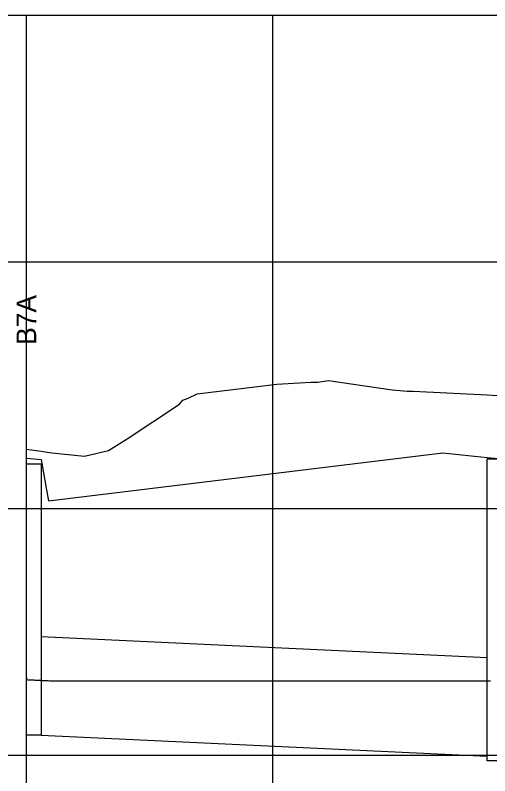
# Model space of a CAD drawing. Extents: x 2254979 to 2278074, y 13790855 to 13792793.
# Drawn here: x 2277948.3 to 2277996.4, y 13792714.2 to 13792791.3 of the extents above; entities that cross this region are included whole.
import ezdxf

# ---------------------------------------------------------------- set-up
doc = ezdxf.new("R2010")
doc.units = 0
for name, color, linetype in [('blank4', 7, 'Continuous'), ('BORD_grid_bottom_major_5int', 7, 'Continuous'), ('D_DRN_PROF_HGL', 7, 'Continuous'), ('D_PROF_1', 7, 'Continuous'), ('D_PROF_NOTES_1', 7, 'Continuous'), ('Drain_PipeInside', 7, 'Continuous'), ('E_Terrain', 7, 'Continuous'), ('Inlet', 7, 'Continuous'), ('z - Construction', 7, 'Continuous')]:
    doc.layers.add(name, color=color, linetype=linetype)

msp = doc.modelspace()

# ---------------------------------------------------------------- linework, layer by layer
at = {"layer": 'blank4'}
msp.add_lwpolyline([(2277949.404, 13792691.266), (2277949.404, 13792766.266), (2278029.904, 13792766.266), (2278029.904, 13792691.266)], close=True, dxfattribs=at)
at = {"layer": 'BORD_grid_bottom_major_5int'}
for p, q in [((2277749.404, 13792791.266), (2278074.404, 13792791.266)), ((2277949.404, 13792491.266), (2277949.404, 13792791.266)), ((2277974.404, 13792491.266), (2277974.404, 13792791.266)), ((2277749.404, 13792766.266), (2278074.404, 13792766.266)), ((2277749.404, 13792741.266), (2278074.404, 13792741.266)), ((2277749.404, 13792716.266), (2278074.404, 13792716.266))]:
    msp.add_line(p, q, dxfattribs=at)
at = {"layer": 'D_DRN_PROF_HGL'}
msp.add_lwpolyline([(2277949.404, 13792724.148), (2277949.404, 13792723.932), (2277949.432, 13792723.935), (2277949.536, 13792723.93), (2277949.641, 13792723.925), (2277949.745, 13792723.92), (2277949.85, 13792723.915), (2277949.954, 13792723.911), (2277950.059, 13792723.906), (2277950.163, 13792723.901), (2277950.268, 13792723.896), (2277950.372, 13792723.891), (2277950.477, 13792723.886), (2277950.581, 13792723.882), (2277950.686, 13792723.877), (2277950.79, 13792723.872), (2277950.895, 13792723.867), (2277950.999, 13792723.862), (2277951.104, 13792723.858), (2277951.208, 13792723.853), (2277951.313, 13792723.848), (2277951.417, 13792723.843), (2277951.522, 13792723.838), (2277951.627, 13792723.833), (2277951.731, 13792723.829), (2277951.836, 13792723.824), (2277951.94, 13792723.819), (2277952.045, 13792723.814), (2277952.15, 13792723.809), (2277952.254, 13792723.805), (2277952.359, 13792723.8), (2277952.463, 13792723.798), (2277952.568, 13792723.798), (2277952.673, 13792723.798), (2277952.777, 13792723.798), (2277952.882, 13792723.798), (2277952.987, 13792723.798), (2277953.091, 13792723.798), (2277953.196, 13792723.798), (2277953.301, 13792723.798), (2277953.406, 13792723.798), (2277953.51, 13792723.798), (2277953.615, 13792723.799), (2277953.72, 13792723.799), (2277953.824, 13792723.799), (2277953.929, 13792723.799), (2277954.034, 13792723.799), (2277954.139, 13792723.799), (2277954.243, 13792723.799), (2277954.348, 13792723.799), (2277954.453, 13792723.799), (2277954.558, 13792723.799), (2277954.663, 13792723.799), (2277954.767, 13792723.799), (2277954.872, 13792723.8), (2277954.977, 13792723.8), (2277955.082, 13792723.8), (2277955.187, 13792723.8), (2277955.291, 13792723.8), (2277955.396, 13792723.8), (2277955.501, 13792723.8), (2277955.606, 13792723.8), (2277955.711, 13792723.8), (2277955.816, 13792723.8), (2277955.921, 13792723.8), (2277956.025, 13792723.8), (2277956.13, 13792723.8), (2277956.235, 13792723.801), (2277956.34, 13792723.801), (2277956.445, 13792723.801), (2277956.55, 13792723.801), (2277956.655, 13792723.801), (2277956.76, 13792723.801), (2277956.865, 13792723.801), (2277956.97, 13792723.801), (2277957.075, 13792723.801), (2277957.179, 13792723.801), (2277957.284, 13792723.801), (2277957.389, 13792723.801), (2277957.494, 13792723.801), (2277957.599, 13792723.801), (2277957.704, 13792723.802), (2277957.809, 13792723.802), (2277957.914, 13792723.802), (2277958.019, 13792723.802), (2277958.124, 13792723.802), (2277958.229, 13792723.802), (2277958.334, 13792723.802), (2277958.439, 13792723.802), (2277958.544, 13792723.802), (2277958.649, 13792723.802), (2277958.754, 13792723.802), (2277958.859, 13792723.802), (2277958.964, 13792723.802), (2277959.069, 13792723.802), (2277959.174, 13792723.802), (2277959.279, 13792723.803), (2277959.385, 13792723.803), (2277959.49, 13792723.803), (2277959.595, 13792723.803), (2277959.7, 13792723.803), (2277959.805, 13792723.803), (2277959.91, 13792723.803), (2277960.015, 13792723.803), (2277960.12, 13792723.803), (2277960.225, 13792723.803), (2277960.33, 13792723.803), (2277960.435, 13792723.803), (2277960.541, 13792723.803), (2277960.646, 13792723.803), (2277960.751, 13792723.803), (2277960.856, 13792723.804), (2277960.961, 13792723.804), (2277961.066, 13792723.804), (2277961.171, 13792723.804), (2277961.277, 13792723.804), (2277961.382, 13792723.804), (2277961.487, 13792723.804), (2277961.592, 13792723.804), (2277961.697, 13792723.804), (2277961.802, 13792723.804), (2277961.908, 13792723.804), (2277962.013, 13792723.804), (2277962.118, 13792723.804), (2277962.223, 13792723.804), (2277962.328, 13792723.804), (2277962.434, 13792723.804), (2277962.539, 13792723.804), (2277962.644, 13792723.805), (2277962.749, 13792723.805), (2277962.854, 13792723.805), (2277962.96, 13792723.805), (2277963.065, 13792723.805), (2277963.17, 13792723.805), (2277963.275, 13792723.805), (2277963.381, 13792723.805), (2277963.486, 13792723.805), (2277963.591, 13792723.805), (2277963.696, 13792723.805), (2277963.802, 13792723.805), (2277963.907, 13792723.805), (2277964.012, 13792723.805), (2277964.118, 13792723.805), (2277964.223, 13792723.805), (2277964.328, 13792723.805), (2277964.433, 13792723.806), (2277964.539, 13792723.806), (2277964.644, 13792723.806), (2277964.749, 13792723.806), (2277964.855, 13792723.806), (2277964.96, 13792723.806), (2277965.065, 13792723.806), (2277965.171, 13792723.806), (2277965.276, 13792723.806), (2277965.381, 13792723.806), (2277965.487, 13792723.806), (2277965.592, 13792723.806), (2277965.697, 13792723.806), (2277965.803, 13792723.806), (2277965.908, 13792723.806), (2277966.013, 13792723.806), (2277966.119, 13792723.806), (2277966.224, 13792723.806), (2277966.33, 13792723.806), (2277966.435, 13792723.807), (2277966.54, 13792723.807), (2277966.646, 13792723.807), (2277966.751, 13792723.807), (2277966.857, 13792723.807), (2277966.962, 13792723.807), (2277967.067, 13792723.807), (2277967.173, 13792723.807), (2277967.278, 13792723.807), (2277967.384, 13792723.807), (2277967.489, 13792723.807), (2277967.594, 13792723.807), (2277967.7, 13792723.807), (2277967.805, 13792723.807), (2277967.911, 13792723.807), (2277968.016, 13792723.807), (2277968.122, 13792723.807), (2277968.227, 13792723.807), (2277968.333, 13792723.807), (2277968.438, 13792723.807), (2277968.543, 13792723.807), (2277968.649, 13792723.808), (2277968.754, 13792723.808), (2277968.86, 13792723.808), (2277968.965, 13792723.808), (2277969.071, 13792723.808), (2277969.176, 13792723.808), (2277969.282, 13792723.808), (2277969.387, 13792723.808), (2277969.493, 13792723.808), (2277969.598, 13792723.808), (2277969.704, 13792723.808), (2277969.809, 13792723.808), (2277969.915, 13792723.808), (2277970.02, 13792723.808), (2277970.126, 13792723.808), (2277970.231, 13792723.808), (2277970.337, 13792723.808), (2277970.442, 13792723.808), (2277970.548, 13792723.808), (2277970.653, 13792723.808), (2277970.759, 13792723.808), (2277970.865, 13792723.808), (2277970.97, 13792723.809), (2277971.076, 13792723.809), (2277971.181, 13792723.809), (2277971.287, 13792723.809), (2277971.392, 13792723.809), (2277971.498, 13792723.809), (2277971.603, 13792723.809), (2277971.709, 13792723.809), (2277971.815, 13792723.809), (2277971.92, 13792723.809), (2277972.026, 13792723.809), (2277972.131, 13792723.809), (2277972.237, 13792723.809), (2277972.343, 13792723.809), (2277972.448, 13792723.809), (2277972.554, 13792723.809), (2277972.659, 13792723.809), (2277972.765, 13792723.809), (2277972.871, 13792723.809), (2277972.976, 13792723.809), (2277973.082, 13792723.809), (2277973.187, 13792723.809), (2277973.293, 13792723.809), (2277973.399, 13792723.809), (2277973.504, 13792723.81), (2277973.61, 13792723.81), (2277973.715, 13792723.81), (2277973.821, 13792723.81), (2277973.927, 13792723.81), (2277974.032, 13792723.81), (2277974.138, 13792723.81), (2277974.244, 13792723.81), (2277974.349, 13792723.81), (2277974.455, 13792723.81), (2277974.561, 13792723.81), (2277974.666, 13792723.81), (2277974.772, 13792723.81), (2277974.878, 13792723.81), (2277974.983, 13792723.81), (2277975.089, 13792723.81), (2277975.195, 13792723.81), (2277975.3, 13792723.81), (2277975.406, 13792723.81), (2277975.512, 13792723.81), (2277975.617, 13792723.81), (2277975.723, 13792723.81), (2277975.829, 13792723.81), (2277975.935, 13792723.81), (2277976.04, 13792723.81), (2277976.146, 13792723.81), (2277976.252, 13792723.811), (2277976.357, 13792723.811), (2277976.463, 13792723.811), (2277976.569, 13792723.811), (2277976.675, 13792723.811), (2277976.78, 13792723.811), (2277976.886, 13792723.811), (2277976.992, 13792723.811), (2277977.097, 13792723.811), (2277977.203, 13792723.811), (2277977.309, 13792723.811), (2277977.415, 13792723.811), (2277977.52, 13792723.811), (2277977.626, 13792723.811), (2277977.732, 13792723.811), (2277977.838, 13792723.811), (2277977.943, 13792723.811), (2277978.049, 13792723.811), (2277978.155, 13792723.811), (2277978.261, 13792723.811), (2277978.366, 13792723.811), (2277978.472, 13792723.811), (2277978.578, 13792723.811), (2277978.684, 13792723.811), (2277978.79, 13792723.811), (2277978.895, 13792723.811), (2277979.001, 13792723.811), (2277979.107, 13792723.811), (2277979.213, 13792723.811), (2277979.318, 13792723.811), (2277979.424, 13792723.812), (2277979.53, 13792723.812), (2277979.636, 13792723.812), (2277979.742, 13792723.812), (2277979.847, 13792723.812), (2277979.953, 13792723.812), (2277980.059, 13792723.812), (2277980.165, 13792723.812), (2277980.271, 13792723.812), (2277980.377, 13792723.812), (2277980.482, 13792723.812), (2277980.588, 13792723.812), (2277980.694, 13792723.812), (2277980.8, 13792723.812), (2277980.906, 13792723.812), (2277981.012, 13792723.812), (2277981.117, 13792723.812), (2277981.223, 13792723.812), (2277981.329, 13792723.812), (2277981.435, 13792723.812), (2277981.541, 13792723.812), (2277981.647, 13792723.812), (2277981.752, 13792723.812), (2277981.858, 13792723.812), (2277981.964, 13792723.812), (2277982.07, 13792723.812), (2277982.176, 13792723.812), (2277982.282, 13792723.812), (2277982.388, 13792723.812), (2277982.493, 13792723.812), (2277982.599, 13792723.812), (2277982.705, 13792723.812), (2277982.811, 13792723.812), (2277982.917, 13792723.812), (2277983.023, 13792723.813), (2277983.129, 13792723.813), (2277983.235, 13792723.813), (2277983.34, 13792723.813), (2277983.446, 13792723.813), (2277983.552, 13792723.813), (2277983.658, 13792723.813), (2277983.764, 13792723.813), (2277983.87, 13792723.813), (2277983.976, 13792723.813), (2277984.082, 13792723.813), (2277984.188, 13792723.813), (2277984.294, 13792723.813), (2277984.399, 13792723.813), (2277984.505, 13792723.813), (2277984.611, 13792723.813), (2277984.717, 13792723.813), (2277984.823, 13792723.813), (2277984.929, 13792723.813), (2277985.035, 13792723.813), (2277985.141, 13792723.813), (2277985.247, 13792723.813), (2277985.353, 13792723.813), (2277985.459, 13792723.813), (2277985.565, 13792723.813), (2277985.671, 13792723.813), (2277985.777, 13792723.813), (2277985.882, 13792723.813), (2277985.988, 13792723.813), (2277986.094, 13792723.813), (2277986.2, 13792723.813), (2277986.306, 13792723.813), (2277986.412, 13792723.813), (2277986.518, 13792723.813), (2277986.624, 13792723.813), (2277986.73, 13792723.813), (2277986.836, 13792723.813), (2277986.942, 13792723.813), (2277987.048, 13792723.814), (2277987.154, 13792723.814), (2277987.26, 13792723.814), (2277987.366, 13792723.814), (2277987.472, 13792723.814), (2277987.578, 13792723.814), (2277987.684, 13792723.814), (2277987.79, 13792723.814), (2277987.896, 13792723.814), (2277988.002, 13792723.814), (2277988.108, 13792723.814), (2277988.214, 13792723.814), (2277988.32, 13792723.814), (2277988.426, 13792723.814), (2277988.532, 13792723.814), (2277988.638, 13792723.814), (2277988.744, 13792723.814), (2277988.85, 13792723.814), (2277988.956, 13792723.814), (2277989.062, 13792723.814), (2277989.168, 13792723.814), (2277989.274, 13792723.814), (2277989.38, 13792723.814), (2277989.486, 13792723.814), (2277989.592, 13792723.814), (2277989.698, 13792723.814), (2277989.804, 13792723.814), (2277989.91, 13792723.814), (2277990.016, 13792723.814), (2277990.122, 13792723.814), (2277990.228, 13792723.814), (2277990.334, 13792723.814), (2277990.44, 13792723.814), (2277990.546, 13792723.814), (2277990.652, 13792723.814), (2277990.758, 13792723.814), (2277990.864, 13792723.814), (2277990.97, 13792723.814), (2277991.076, 13792723.814), (2277991.182, 13792723.814), (2277991.288, 13792723.814), (2277991.394, 13792723.814), (2277991.5, 13792723.814), (2277991.606, 13792723.814), (2277991.712, 13792723.814), (2277991.819, 13792723.814), (2277991.925, 13792723.814), (2277992.031, 13792723.815), (2277992.137, 13792723.815), (2277992.243, 13792723.815), (2277992.349, 13792723.815), (2277992.455, 13792723.815), (2277992.561, 13792723.815), (2277992.667, 13792723.815), (2277992.773, 13792723.815), (2277992.879, 13792723.815), (2277992.985, 13792723.815), (2277993.091, 13792723.815), (2277993.197, 13792723.815), (2277993.304, 13792723.815), (2277993.41, 13792723.815), (2277993.516, 13792723.815), (2277993.622, 13792723.815), (2277993.728, 13792723.815), (2277993.834, 13792723.815), (2277993.94, 13792723.815), (2277994.046, 13792723.815), (2277994.152, 13792723.815), (2277994.258, 13792723.815), (2277994.364, 13792723.815), (2277994.471, 13792723.815), (2277994.577, 13792723.815), (2277994.683, 13792723.815), (2277994.789, 13792723.815), (2277994.895, 13792723.815), (2277995.001, 13792723.815), (2277995.107, 13792723.815), (2277995.213, 13792723.815), (2277995.319, 13792723.815), (2277995.426, 13792723.815), (2277995.532, 13792723.815), (2277995.638, 13792723.815), (2277995.744, 13792723.815), (2277995.85, 13792723.815), (2277995.956, 13792723.815), (2277996.062, 13792723.815), (2277996.168, 13792723.815), (2277996.275, 13792723.815), (2277996.381, 13792723.815), (2277996.487, 13792723.815)], dxfattribs=at)
at = {"layer": 'D_PROF_1'}
msp.add_lwpolyline([(2277949.404, 13792746.385), (2277950.904, 13792746.235), (2277950.904, 13792746.235), (2277950.904, 13792746.235), (2277951.425, 13792743.342), (2277951.654, 13792742.069), (2277991.654, 13792746.902), (2277996.154, 13792746.452), (2277996.154, 13792746.452), (2277997.654, 13792746.302), (2277997.654, 13792746.302), (2277999.154, 13792746.152), (2277999.154, 13792746.152), (2278027.654, 13792743.302), (2278027.884, 13792744.32), (2278028.404, 13792746.635), (2278028.404, 13792746.635), (2278029.904, 13792746.785)], dxfattribs=at)
at = {"layer": 'Drain_PipeInside'}
for p, q in [((2277950.904, 13792728.316), (2277996.154, 13792726.191)), ((2277950.904, 13792718.316), (2277996.154, 13792716.191))]:
    msp.add_line(p, q, dxfattribs=at)
at = {"layer": 'E_Terrain'}
msp.add_lwpolyline([(2277949.404, 13792747.296), (2277950.904, 13792747.082), (2277950.904, 13792747.082), (2277951.975, 13792746.93), (2277955.306, 13792746.59), (2277957.731, 13792747.161), (2277959.612, 13792748.326), (2277964.936, 13792751.867), (2277965.275, 13792752.242), (2277965.823, 13792752.461), (2277966.71, 13792752.904), (2277974.791, 13792753.861), (2277978.266, 13792754.087), (2277978.469, 13792754.085), (2277978.947, 13792754.087), (2277980.034, 13792754.251), (2277986.512, 13792753.294), (2277988.025, 13792753.159), (2277988.21, 13792753.173), (2277988.636, 13792753.169), (2277996.154, 13792752.781), (2277996.154, 13792752.781), (2277997.654, 13792752.704)], dxfattribs=at)
at = {"layer": 'Inlet'}
for points in [[(2277996.154, 13792746.302), (2277999.154, 13792746.302), (2277999.154, 13792715.691), (2277996.154, 13792715.691)], [(2277949.404, 13792745.819), (2277950.904, 13792745.819), (2277950.904, 13792718.316), (2277949.404, 13792718.316)]]:
    msp.add_lwpolyline(points, close=True, dxfattribs=at)
at = {"layer": 'z - Construction'}
for p, q in [((2277949.404, 13792741.266), (2278029.904, 13792741.266)), ((2277949.404, 13792716.266), (2278029.904, 13792716.266))]:
    msp.add_line(p, q, dxfattribs=at)

# ---------------------------------------------------------------- texts
at = {"layer": 'D_PROF_NOTES_1'}
msp.add_text('B7A', height=2, rotation=90, dxfattribs=at).set_placement((2277950.404, 13792757.86))

doc.saveas('drawing.dxf')
